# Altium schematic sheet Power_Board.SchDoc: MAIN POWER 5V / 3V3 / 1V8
size A4; Date: Not used; ApprovedBy: Not used; CheckedBy: Not used; Author: Not used; CompanyName: STMicroelectronics; DrawnBy: Not used; Engineer: Not used; Organization: Not used; Address1: Not used; Address2: Not used; Address3: Not used; Address4: Not used; DocumentNumber: 9; Revision: Not used; SheetNumber: 8; SheetTotal: 9
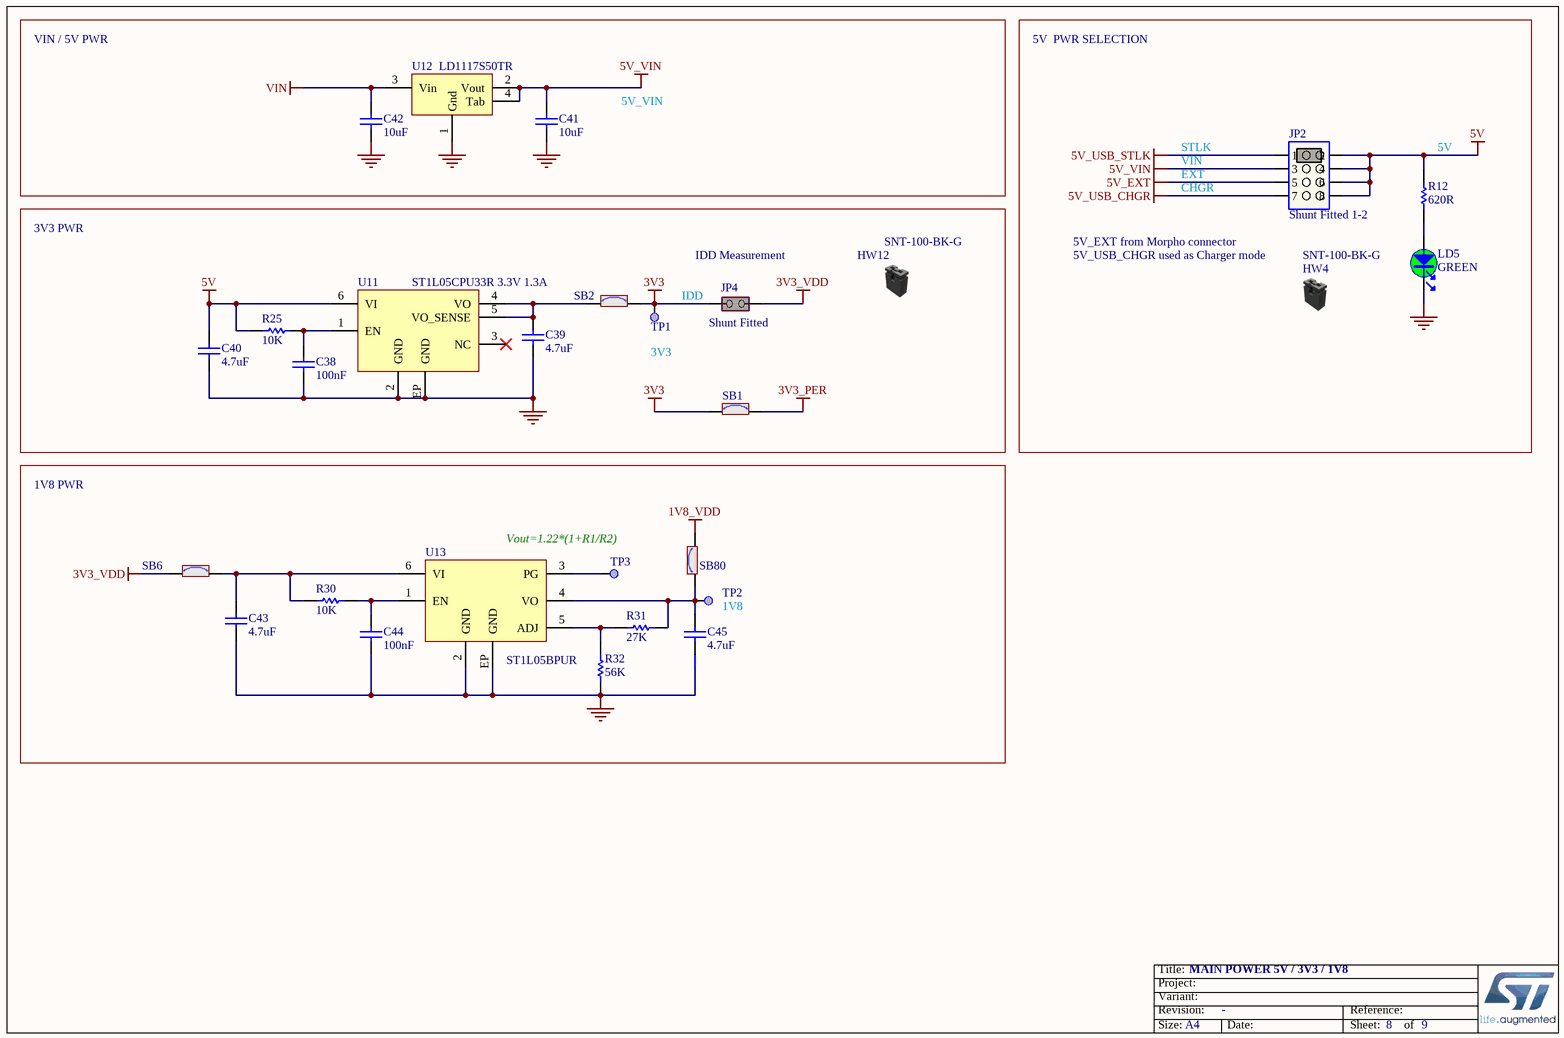
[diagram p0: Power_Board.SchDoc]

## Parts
C38  value 100nF  [C0402]  (hidden comment: Capacitor)
C39  value 4.7uF  [C0603]  (hidden comment: Capacitor)
C40  value 4.7uF  [C0603]  (hidden comment: Capacitor)
C41  value 10uF  [C0805]  (hidden comment: Capacitor)
C42  value 10uF  [C0805]  (hidden comment: Capacitor)
C43  value 4.7uF  [C0603]  (hidden comment: Capacitor)
C44  value 100nF  [C0603]  (hidden comment: Capacitor)
C45  value 4.7uF  [C0603]  (hidden comment: Capacitor)
HW4  value SNT-100-BK-G  (hidden comment: Shunt Black 2.54mm)  (mechanical)
HW12  value SNT-100-BK-G  (hidden comment: Shunt Black 2.54mm)  (mechanical)
JP2  value Shunt Fitted 1-2  [CON_SAMTEC_TSW-104-07-X-D]  (hidden comment: Jumper_Header 4x2 Fitted 1-2)
JP4  value Shunt Fitted  [CON_SAMTEC_TSW-102-07-G-S]  (hidden comment: Jumper_Header 2x1 Fitted)
LD5  value GREEN  [LED_0603_OSRAM_LG-Q396-PS-35_GREEN_1A2K_H0P4]  (hidden comment: LED_green)
R12  value 620R  [R0603]  (hidden comment: Resistor)
R25  value 10K  [R0402]  (hidden comment: Resistor)
R30  value 10K  [R0402]  (hidden comment: Resistor)
R31  value 27K  [R0402]  (hidden comment: Resistor)
R32  value 56K  [R0402]  (hidden comment: Resistor)
SB1  SB_ON  [SOLDER-BRIDGE_R0603-0R]  (value not drawn)
SB2  SB_ON  [SOLDER-BRIDGE_R0603-0R]  (value not drawn)
SB6  SB_ON  [SOLDER-BRIDGE_R0603-0R]  (value not drawn)
SB80  SB_ON  [SOLDER-BRIDGE_R0603-0R]  (value not drawn)
TP1  Test Point  [TP_SMD_1MM]  (value not drawn)  (no BOM)
TP2  Test Point  [TP_SMD_1MM]  (value not drawn)  (no BOM)
TP3  Test Point  [TP_SMD_1MM]  (value not drawn)  (no BOM)
U11  value ST1L05CPU33R 3.3V 1.3A  [ICC_DFN6-EPAD_3X3_P095]  (hidden comment: ST1L05CPU33R)
U12  LD1117S50TR  [REG_SOT223-TAB]
U13  ST1L05BPUR  [ICC_DFN6-EPAD_3X3_P095]

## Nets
1V8_VDD: SB80.2
3V3: JP4.1(COMMON) SB1.1 SB2.2 TP1.1
3V3_PER: SB1.2
3V3_VDD: JP4.2(NO) SB6.1
5V: C40.2 JP2.2 JP2.4 JP2.6 JP2.8 R12.2 R25.2 U11.6(VI)
5V_EXT: JP2.5
5V_USB_CHGR: JP2.7
5V_USB_STLK: JP2.1
5V_VIN: C41.2 JP2.3 U12.2(Vout) U12.4(Tab)
GND: C38.2 C39.1 C40.1 C41.1 C42.1 C43.1 C44.1 C45.1 LD5.2 R32.1 U11.2(GND) U11.EP(GND) U12.1(Gnd) U13.2(GND) U13.EP(GND)
VIN: C42.2 U12.3(Vin)
NetC38_1: C38.1 R25.1 U11.1(EN)
NetC39_2: C39.2 SB2.1 U11.4(VO) U11.5(VO_SENSE)
NetC43_2: C43.2 R30.2 SB6.2 U13.6(VI)
NetC44_2: C44.2 R30.1 U13.1(EN)
NetC45_2: C45.2 R31.2 SB80.1 TP2.1 U13.4(VO)
NetLD5_1: LD5.1 R12.1
NetR31_1: R31.1 R32.2 U13.5(ADJ)
NetTP3_1: TP3.1 U13.3(PG)

Not connected (* = marked no-connect by the designer): U11 3(NC)*

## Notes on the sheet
- VIN / 5V PWR
- 5V  PWR SELECTION
- 5V_VIN
- STLK
- VIN
- EXT
- (near R12) 5V
- 3V3 PWR
- 5V_EXT from Morpho connector
- CHGR
- IDD
- (near JP4) IDD Measurement
- 5V_USB_CHGR used as Charger mode
- (near TP1) 3V3
- 1V8 PWR
- Vout=1.22*(1+R1/R2)
- (near TP2) 1V8

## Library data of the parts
C38 = MCD-00006: Capacitor, MLCC, 100nF, 16V, X7R, 10%, 0402, T=0.5mm; Manufacturer_Part_Number: CC0402KRX7R7BB104; Manufacturer: YAGEO; Alternate_Manufacturer_Part_Number: GCM155R71C104KA55D; Alternate_Manufacturer: MURATA; Provided_By: SUBCO; ECCN_US: EAR99; ECCN_EU: NEC
C39 C45 = MCD-01121: Capacitor, MLCC, 4.7µF, 10V, X5R, 20%, 0603, T=0,8mm; Manufacturer_Part_Number: GRM188R61A475ME15; Manufacturer: MURATA; Provided_By: SUBCO; ECCN_US: EAR99; ECCN_EU: NEC
C40 C43 = MCD-00097: Capacitor, MLCC, 4.7uF, 16V, X5R, 20%, 0603, T=0,8mm; Manufacturer_Part_Number: GRM188R61C475KE11; Manufacturer: MURATA; Alternate_Manufacturer_Part_Number: GRM188R61C475MAAJ; Provided_By: SUBCO; ECCN_US: EAR99; ECCN_EU: NEC
C41 C42 = MCD-00014: Capacitor, MLCC, 10uF, 25V, X5R, 10%, 0805, T=0,85mm; Manufacturer_Part_Number: CC0805KRX5R8BB106; Manufacturer: YAGEO; Provided_By: SUBCO; ECCN_US: EAR99; ECCN_EU: NEC
C44 = MCD-00237: Capacitor, MLCC, 100nF, 6V3, X5R, 10%, 0603, T=0,8mm; Manufacturer_Part_Number: CC0603KRX5R5BB104; Manufacturer: YAGEO; Provided_By: SUBCO; ECCN_US: EAR99; ECCN_EU: NEC
HW4 HW12 = MCD-00043: SHUNT 2.54mm BLACK; Manufacturer: SAMTEC; Part_Type: Mechanical; Alternate_Manufacturer_Part_Number: 316102S111A; Alternate_Manufacturer: JIUBABA; Provided_By: SUBCO
JP2 = MCD-00686: Header, 4x2, 2,54mm, VR, TH, Height 5.84mm/2.54mm - Shunt Fitted 1-2; Part_Type: Connector; Manufacturer_Part_Number: TSW-104-07-x-D; Manufacturer: SAMTEC; Provided_By: SUBCO
JP4 = MCD-00683: Header, 2x1, 2,54mm, VR, TH, Height 5.84mm/2.54mm - Shunt Fitted by default; Part_Type: Connector; Manufacturer_Part_Number: TSW-102-07-x-S; Manufacturer: SAMTEC; Alternate_Manufacturer_Part_Number: 313102S111116; Alternate_Manufacturer: LIANYI; Provided_By: SUBCO
LD5 = MCD-00588: LED Green, 0603 SMD, Forward Voltage Typ=2V, Max=2.5V; Part_Type: Display; Manufacturer_Part_Number: LG Q396-PS-35; Manufacturer: OSRAM OPTO SEMICONDUCTORS; Alternate_Manufacturer_Part_Number: VLMTG1300-GS08; Alternate_Manufacturer: VISHAY SEMICONDUCTOR OPTO DIVISION; Provided_By: SUBCO
R12 = MCD-00500: Resistor,620R,0603,1%,1/10W; Manufacturer_Part_Number: RC0603FR-07620RL; Manufacturer: YAGEO; Provided_By: SUBCO; ECCN_US: EAR99; ECCN_EU: NEC
R25 R30 = MCD-00053: Resistor,10K,0402,1%,1/16W; Manufacturer_Part_Number: RC0402FR-0710KL; Manufacturer: YAGEO; Provided_By: SUBCO; ECCN_US: EAR99; ECCN_EU: NEC
R31 = MCD-00443: Resistor,27K,0402,1%,1/16W; Manufacturer_Part_Number: RC0402FR-0727KL; Manufacturer: YAGEO; Provided_By: SUBCO; ECCN_US: EAR99; ECCN_EU: NEC
R32 = MCD-00493: Resistor,56K,0402,1%,1/16W; Manufacturer_Part_Number: RC0402FR-0756KL; Manufacturer: YAGEO; Provided_By: SUBCO; ECCN_US: EAR99; ECCN_EU: NEC
SB1 SB2 SB6 SB80 = MCD-00071: Solder Bridge ON; Part_Type: Mechanical; Manufacturer_Part_Number: RC0603JR-070RL; Manufacturer: YAGEO; Provided_By: SUBCO
TP1-TP3 = MCD-00074: Test Point 1mm; Part_Type: Mechanical
U11 = MCD-01025: LDO, 3.3V, 1.3A, Very low quiescent current BiCMOS voltage regulator; Part_Type: IC; Manufacturer: STMICROELECTRONICS; BMS_Part_Number: 9176246; Provided_By: SUBCO with ST control; ECCN_US: EAR99; ECCN_EU: NEC
U12 = MCD-00088: IC REG LDO 5V 0.8A SOT223; Manufacturer: STMICROELECTRONICS; BMS_Part_Number: 9176133; Provided_By: SUBCO with ST control; ECCN_US: EAR99; ECCN_EU: NEC
U13 = MCD-00581: LDO Linear Voltage Regulator IC Positive Adjustable 1 Output Adjustable 1.3A 6-DFN (3x3); Manufacturer: STMICROELECTRONICS; BMS_Part_Number: 9176239; Provided_By: SUBCO with ST control; ECCN_US: EAR99; ECCN_EU: NEC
